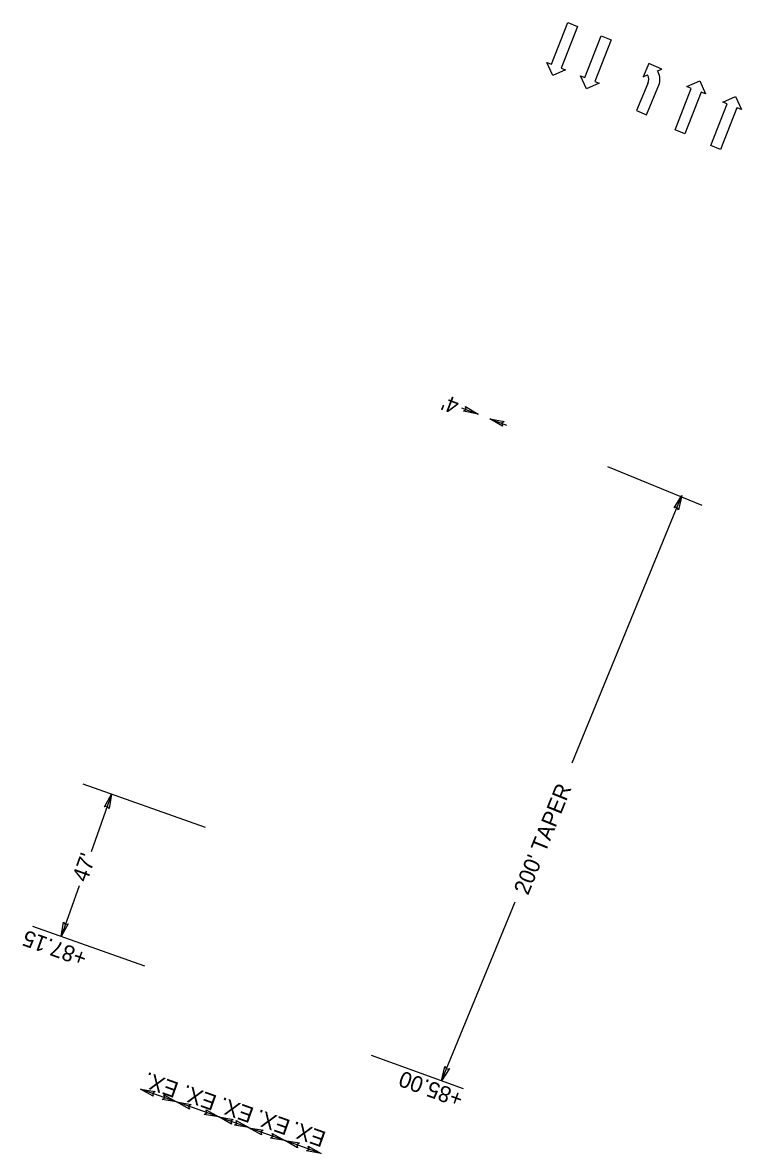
# Model space of a CAD drawing. Extents: x 2320991 to 2332664, y 598057 to 612602.
# Drawn here: x 2328665.8 to 2328891, y 607456.9 to 607810.9 of the extents above; entities that cross this region are included whole.
import ezdxf

# ---------------------------------------------------------------- set-up
doc = ezdxf.new("R2010")
doc.units = 0
for name, color, linetype in [('Prop Dimension', 7, 'Continuous'), ('Prop Dimension Text', 7, 'Continuous'), ('Prop Lane Arrow CELL', 7, 'Continuous'), ('Prop Terminator CELL', 7, 'Continuous')]:
    doc.layers.add(name, color=color, linetype=linetype)

msp = doc.modelspace()

# ---------------------------------------------------------------- linework, layer by layer
at = {"layer": 'Prop Dimension'}
for p, q in [((2328803.33, 607690.33), (2328808.5, 607688.32)), ((2328812.23, 607686.87), (2328817.39, 607684.86)), ((2328878.67, 607659.73), (2328849.18, 607671.78)), ((2328837.98, 607579.15), (2328872.33, 607662.82)), ((2328723.1, 607558.9), (2328684.79, 607572.48)), ((2328693.69, 607569.33), (2328687.28, 607551.29)), ((2328683.51, 607540.57), (2328677.89, 607524.75)), ((2328797.09, 607479.53), (2328820.12, 607535.63)), ((2328704.12, 607515.45), (2328668.99, 607527.9)), ((2328804, 607477.02), (2328775.15, 607487.49)), ((2328714.09, 607472.95), (2328702.79, 607476.97)), ((2328727.28, 607468.26), (2328714.09, 607472.95)), ((2328727.28, 607468.26), (2328736.7, 607464.91)), ((2328748.01, 607460.87), (2328736.7, 607464.89)), ((2328759.31, 607456.85), (2328748.01, 607460.87))]:
    msp.add_line(p, q, dxfattribs=at)
at = {"layer": 'Prop Lane Arrow CELL'}
for p, q in [((2328831.48, 607797.86), (2328836.59, 607810.89)), ((2328839.66, 607809.69), (2328834.55, 607796.65)), ((2328836.59, 607810.89), (2328839.66, 607809.69)), ((2328842, 607793.68), (2328847.11, 607806.71)), ((2328850.18, 607805.51), (2328845.07, 607792.47)), ((2328847.11, 607806.71), (2328850.18, 607805.51)), ((2328831.91, 607794.31), (2328830.08, 607798.41)), ((2328830.08, 607798.41), (2328831.48, 607797.86)), ((2328862.03, 607798.1), (2328860.25, 607793.97)), ((2328866.07, 607796.36), (2328862.03, 607798.1)), ((2328835.95, 607796.11), (2328831.91, 607794.31)), ((2328834.55, 607796.65), (2328835.95, 607796.11)), ((2328842.43, 607790.12), (2328840.61, 607794.23)), ((2328840.61, 607794.23), (2328842, 607793.68)), ((2328860.25, 607793.97), (2328861.62, 607794.53)), ((2328864.69, 607795.8), (2328866.07, 607796.36)), ((2328846.47, 607791.93), (2328842.43, 607790.12)), ((2328845.07, 607792.47), (2328846.47, 607791.93)), ((2328861.72, 607791.78), (2328858.19, 607783.34)), ((2328861.23, 607782.07), (2328865.3, 607791.8)), ((2328870.21, 607777.28), (2328875.32, 607790.31)), ((2328873.92, 607790.86), (2328877.96, 607792.66)), ((2328875.32, 607790.31), (2328873.92, 607790.86)), ((2328877.96, 607792.66), (2328879.78, 607788.56)), ((2328878.39, 607789.11), (2328873.28, 607776.07)), ((2328879.78, 607788.56), (2328878.39, 607789.11)), ((2328885.14, 607786), (2328889.18, 607787.8)), ((2328889.18, 607787.8), (2328891.01, 607783.7)), ((2328858.19, 607783.34), (2328861.23, 607782.07)), ((2328881.43, 607772.42), (2328886.54, 607785.45)), ((2328889.61, 607784.25), (2328884.5, 607771.21)), ((2328886.54, 607785.45), (2328885.14, 607786)), ((2328891.01, 607783.7), (2328889.61, 607784.25)), ((2328873.28, 607776.07), (2328870.21, 607777.28)), ((2328884.5, 607771.21), (2328881.43, 607772.42))]:
    msp.add_line(p, q, dxfattribs=at)
for centre, radius, start, end in [((2328858.71, 607793.05), 3.27, 337.3163, 26.9745), ((2328860.22, 607793.07), 5.25, 345.9924, 31.304)]:
    msp.add_arc(centre, radius, start, end, dxfattribs=at)
at = {"layer": 'Prop Terminator CELL'}
for points in [[(2328804.59, 607690.67), (2328808.5, 607688.32), (2328804, 607689.22), (2328804.82, 607689.75)], [(2328816.14, 607684.51), (2328812.23, 607686.87), (2328816.74, 607685.97), (2328815.91, 607685.44)], [(2328869.9, 607658.95), (2328872.33, 607662.82), (2328871.35, 607658.33), (2328870.83, 607659.16)], [(2328691.45, 607565.35), (2328693.69, 607569.33), (2328692.93, 607564.79), (2328692.37, 607565.6)], [(2328680.13, 607528.73), (2328677.89, 607524.75), (2328678.65, 607529.28), (2328679.21, 607528.47)], [(2328799.52, 607483.39), (2328797.09, 607479.53), (2328798.07, 607484.02), (2328798.59, 607483.18)], [(2328706.77, 607474.73), (2328702.79, 607476.97), (2328707.32, 607476.21), (2328706.51, 607475.65)], [(2328710.11, 607475.19), (2328714.09, 607472.95), (2328709.56, 607473.71), (2328710.37, 607474.28)], [(2328718.07, 607470.71), (2328714.09, 607472.95), (2328718.63, 607472.19), (2328717.82, 607471.63)], [(2328723.3, 607470.5), (2328727.28, 607468.26), (2328722.75, 607469.02), (2328723.56, 607469.58)], [(2328731.26, 607466.02), (2328727.28, 607468.26), (2328731.82, 607467.5), (2328731.01, 607466.94)], [(2328732.73, 607467.15), (2328736.7, 607464.91), (2328732.17, 607465.67), (2328732.98, 607466.23)], [(2328740.68, 607462.66), (2328736.7, 607464.89), (2328741.23, 607464.13), (2328740.42, 607463.57)], [(2328744.03, 607463.11), (2328748.01, 607460.87), (2328743.48, 607461.64), (2328744.28, 607462.2)], [(2328751.99, 607458.63), (2328748.01, 607460.87), (2328752.54, 607460.11), (2328751.73, 607459.55)], [(2328755.33, 607459.09), (2328759.31, 607456.85), (2328754.78, 607457.61), (2328755.59, 607458.18)]]:
    msp.add_lwpolyline(points, close=True, dxfattribs=at)

# ---------------------------------------------------------------- texts
at = {"layer": 'Prop Dimension'}
msp.add_text('+85.00', height=5, rotation=160.0636, dxfattribs=at).set_placement((2328804.3, 607475.78))
at = {"layer": 'Prop Dimension Text'}
for s, rotation, p in [("4'", 158.7253, (2328803.02, 607692.76)), ("200' TAPER", 67.9197, (2328824.16, 607537.45)), ("47'", 70.4456, (2328685.95, 607541.5)), ('+87.15', 160.2768, (2328686.43, 607519.89)), ('EX.', 160.4246, (2328715.08, 607478.83)), ('EX.', 160.4246, (2328727.02, 607474.83)), ('EX.', 160.4246, (2328738.64, 607470.95)), ('EX.', 160.4246, (2328750.05, 607467.13)), ('EX.', 160.4246, (2328761.2, 607463.4))]:
    msp.add_text(s, height=5, rotation=rotation, dxfattribs=at).set_placement(p)

doc.saveas('drawing.dxf')
